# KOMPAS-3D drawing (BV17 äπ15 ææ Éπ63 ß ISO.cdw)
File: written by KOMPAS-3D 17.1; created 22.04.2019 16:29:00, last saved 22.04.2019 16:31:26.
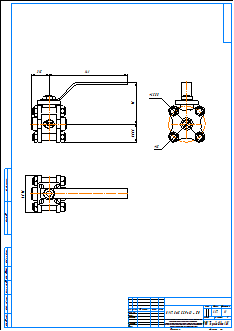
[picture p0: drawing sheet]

Sheet 1: A2, portrait

Title block, sheet 1: name: BV17 Ду15 СС Ру63 с ISO; material: Внимание! Данный продукт является объектом авторского права ООО «Торговый Дом АДЛ». / Запрещается изменение, копирование, распространение / (в том числе путем копирования на другие сайты и ресурсы в Интернете) / или любое иное использование информации и объектов без предварительного / согласия правообладателя (ООО «Торговый Дом АДЛ»).; mass: 1,17; sheets: 1; organisation: ООО "Торговый дом АДЛ"; sheet format: A2

Views: Спереди 1, Проекционный вид 2, Проекционный вид 3
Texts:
  user
Dimensions and other numbers on the sheet: 31,5; 141; 75; 32,89; 65,88; 65,79; 15; 1:1; 1; 1,17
